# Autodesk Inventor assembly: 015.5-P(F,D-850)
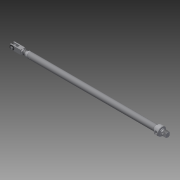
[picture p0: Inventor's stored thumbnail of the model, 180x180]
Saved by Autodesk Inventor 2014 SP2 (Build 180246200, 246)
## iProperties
Category: PARTsolutions
Company: BIMBA
Created: 2020-01
Part Number: 015.5-P(F,D-850)
Catalog Web Link: www.cadenas.de
Description: Original Line Standard Air Cylinders-Standard Air Cylinders
Vendor: BIMBA
Document SubType Name: Assembly
Designer: psadmin
Manufacturer: BIMBA
Title: 015.5-P
Author: Cadenas PARTsolutions
Comments: Standard Air Cylinders
PSOL_IDENT_0: {$CADENAS_DATA\23d-libs\bimba\bimba_brand\bimba_imperial\bimba_full_line\original_line_cylinders\sta
PSOL_IDENT_1: ndard_air_cylinders\standard_air_cylinder_asmtab.prj},331 {VTYP=3D},{STYP=ASSTAB},{NB=015.5-P(F,D-85
PSOL_IDENT_2: 0)},{LINA=015.5-P},{NN=Original Line Standard Air Cylinders},{DATE=23.12.2019 10:36:48},{GEOMDATE=24
PSOL_IDENT_3: .10.2019 09:09:47},{VERSION=},{LINEID=30},{WBVAR=STROKE,ACTING,MNT,DER,NR,BM,CO,OO,VO,M,EE,EEL,K,Q,Y
PSOL_IDENT_4: ,G,T,HL,B,H,SER,SR,NT,W,STPT1,STPT2,STPT3,STPT4,MB,PB,PRC,TB,MN},{WBNUMERIC=STROKE,EEL}  {NB=015.5-P
PSOL_IDENT_5: (F,D-850)},{LINA=015.5-P},{KT=DUMMY},{PN=015.5-P},{PNC=015.5-P(F,D-850)},{PNA=(D-850)},{DASH=-},{BOR
PSOL_IDENT_6: E1=0.43750000},{BORE=7/16\" (01)},{BOREPN=01},{STROKE=5.500},{STROKEALG=[0.011:50/0.001]},{STROKE1=5
PSOL_IDENT_7: .500},{ACTING=},{ACTINGALG= '' , 'Single Acting' , 'R' , 'Reverse Single Acting (R)' , 'D' , 'Double
PSOL_IDENT_8: Acting (D)' },{ACTINGPN=},{MNT=P},{MNTALG= '' , 'Front Nose Mounting' , 'P' , 'Rear Pivot Mounting
PSOL_IDENT_9: (P)' , 'BF' , 'Front Block Mounting (BF)' , 'BR' , 'Rear Block Mounting for Vertical Positioning (BR
PSOL_IDENT_10: )' , 'BFT' , 'Front Block Trunnion Mounting (BFT)' , 'BRT' , 'Rear Block Trunnion Mounting (BRT)' },
PSOL_IDENT_11: {TYPE=},{MNTPN=P},{DER=},{DERALG= '' , 'N/A' },{NR=},{NRALG= '' , 'Round (Standard)' , 'NR' , 'Non-r
PSOL_IDENT_12: otating - Hexagon Rod' },{NRPN=},{BM=},{BMALG= '' , 'N/A' },{BMPN=},{CO=},{COALG= '' , 'N/A' },{OO=}
PSOL_IDENT_13: ,{OOALG= '', 'N/A' },{OOPN=},{VO=Z},{VOALG= 'Z' , 'N/A' },{VOPN=},{OOVOPN=},{M=},{MALG= '', 'Without
PSOL_IDENT_14: Magnet', 'M', 'With Magnet' },{EE=},{EEL=0.000},{EEMAX=44.5000},{EEALG= '', 'Without Extra Extensio
PSOL_IDENT_15: n', 'EE', 'With Extra Extension' },{EELALG=0},{EEPN=},{EEPN1=0.000},{K=},{KALG= '', 'Standard' , 'K'
PSOL_IDENT_16: , 'Ports Rotated 90deg K' },{KPN=},{Q=},{QALG= '' , 'N/A' },{QPN=},{Y=},{YALG= '' , 'Without Pivot
PSOL_IDENT_17: Bushing' , 'Y' , 'With Pivot Bushing' },{YPN=},{YCON=},{F=},{FALG= '', 'Non-Coated (Standard)', 'F',
PSOL_IDENT_18: 'Molycoated' },{FPN=},{G=},{GPN=},{GPN99=},{T=},{TALG= '' , 'Standard -20° to 200°F (-29° to 95°C)'
PSOL_IDENT_19: , 'N' , 'Low Temperature' , 'V' , 'High Temperature' },{NPN=},{VPN=},{HL=},{HLALG= '' , 'N/A' },{B=
PSOL_IDENT_20: },{BALG= '', 'W/out Bumpers' , 'B' , 'W/ Bumpers' },{BPN=},{H=},{HALG= '', 'N/A' },{HPN=},{SER=},{SE
PSOL_IDENT_21: RALG= '' , 'N/A' },{SR=},{SRALG= '' , 'Standard Stainless Steel' },{SRPN=},{SRCON=0},{NT=},{NTPN=},{
PSOL_IDENT_22: W=},{WALG= '' , 'N/A' },{WPN=},{E=},{EALG= '' , 'Standard Seals/Lube' , 'E' , 'Non-Lube Seals/Lube'
PSOL_IDENT_23: },{EPN=},{ST=},{STALG= '' , 'N/A' },{STPT1=},{STPT1ALG= '' , 'N/A' },{STPT2=},{STPT2ALG= '' , 'N/A'
PSOL_IDENT_24: },{STPT3=},{STPT3ALG= '' , 'N/A' },{STPT4=},{STPT4ALG= '' , 'N/A' },{STPN=},{MB=},{MBALG= '' , 'N/A'
PSOL_IDENT_25: },{MBPN=},{MBPNALL=},{MBPNALLREAR=},{PB=},{PBALG= '' , 'Without Pivot Bracket' , 'D-780' , 'D-780'
PSOL_IDENT_26: },{PBPN=},{PBPNALL=D-780},{PRC=F,D-850},{PRCALG= '' , 'W/out Pivot Rod Clevis' , 'F,D-850' , 'D-850
PSOL_IDENT_27: (front)' },{PRCPN=(F,D-850)},{PRCPNALL=D-850},{TB=},{TBALG= '' , 'N/A' },{TBPN=},{TBPNALL=},{MN=},{M
PSOL_IDENT_28: NALG= '' , 'Without Mounting Nut' , 'F,D-801' , 'D-801 (front)' , 'R,D-154' , 'D-154 (rear)', '2xZ'
PSOL_IDENT_29: , 'D-801 (front) & D-154 (rear)' },{MNPN=},{MNCONF=},{MNCONR=},{TLEN=10.8620},{FRAC=12.0900},{RGCON=
PSOL_IDENT_30: },{RGDACCON=},{RHCON=P},{RHCON1=P},{RHCONON=1},{RHACCON=},{FNUTCON=0},{RNUTCON=0},{FNUTPN=D-801},{RN
PSOL_IDENT_31: UTPN=D-154},{FNUTTRANS=0.0000},{RNUTTRANS=0.0000},{VHOLECON=2},{A1=0.6880},{A1N=0.6880},{A1P=1.1880}
PSOL_IDENT_32: ,{A1B=1.1880},{A4=0.2500},{A4N=0.2500},{A4P=0.1880},{A5=0.0200},{A1H=1.188},{A1NH=0.5000},{A1PH=1.18
PSOL_IDENT_33: 80},{A1BH=0.8120},{A1SH=0.0000},{A2H=0.1880},{A2NH=0.1880},{LENGTH=1.7500},{LENGTH1=1.7500},{LENGTH2=
PSOL_IDENT_34: 2.6100},{MUL=10.3400},{MUL11=10.3400},{MUL22=15.84},{MUL33=10.3400},{MUL2=0.9400},{MUL211=0.9400},{M
PSOL_IDENT_35: UL222=1.4400},{MUL233=0.9400},{SSS=11.0000},{RGLEN=0.4580},{RHLEN=0.7700},{SSS1=11.0000},{A13=0.9380
PSOL_IDENT_36: },{DIF=0.0000},{G5=0.0000},{ON=0},{SSADD=0.0000},{BADD=0.0000},{MADD=0.0000},{NVADD=0.0000},{TRACKL=
PSOL_IDENT_37: 10.5520},{TRACKCON=D-74168},{TRIMCON=0},{TRIMCON1=0},{PINCON=D-787},{FSPACE=0.3608},{SPACE=0.0594},{
PSOL_IDENT_38: TEXT=0.1039},{S1=0.7500},{D1=0.4840},{D1N=0.4840},{D1B=0.7380},{D1P=0.0000},{FA=0.560},{RA=0.5600},{
PSOL_IDENT_39: PPATH=standard_air_cylinder_asmtpl.prj},{MATALGHTML=<b>Standard Original Line:</b><dl><dt>Rod:</dt><
PSOL_IDENT_40: dd>- Stainless Steel</dd><dd>&nbsp;&nbsp;(5/16 9/16 Bores)</dd><dd>- High Strength Carbon Steel</dd>
PSOL_IDENT_41: <dd>&nbsp;&nbsp;(3/4 3 Bore)</dd><dd>- Stainless Steel</dd><dd>&nbsp;&nbsp;(X style DXP/DX/DXDE)</dd
PSOL_IDENT_42: ><dt>Bearings:</dt><dd>- Sintered Bronze</dd><dt>Body:</dt><dd>- 304 Stainless Steel</dd><dt>End Cap
PSOL_IDENT_43: s:</dt><dd>- Aluminum</dd><dt>Seals:</dt><dd>- Buna N</dd></dl>},{ASSCFGPRA=01P},{MBPNA=},{MNPNA=},{
PSOL_IDENT_44: PRCPNA=(D-850)},{ASSOPTACC=STPT4},{A=12.09},{HADD=0.0000},{WFL=0},{QADD=0.000},{QADD1=0.190},{TEST=5
PSOL_IDENT_45: .0000},{MNTB=},{STDNUTF=0},{STDNUTR=0},{STRK2D=0},{X2D=2},{STROKESW=5.500},{EESW=0.000},{FCD=0},{BCD=
PSOL_IDENT_46: 0},{RCD=0},{CUSTADD=4.500},{FT=#10-32 UNF-2A},{FT1=#10-32 UNF-2A},{FT2=7/16-20 UNF-2A},{PORT=#10-32}
PSOL_IDENT_47: ,{FT11=3/8-24 UNF-2A},{FT12=7/16-20 UNF-2A},{B1=}
NN: Original Line Standard Air Cylinders
NT: Threaded (Standard)
NB: 015.5-P(F,D-850)
NBSYN: $PNC.
LINA: 015.5-P
PN: 015.5-P
PNA: (D-850)
BORE: 7/16" (01)
STROKE: 5.5
ACTING: Single [Standard]
MNT: Rear Pivot Mounting (P)
DER: N/A
NR: Round (Standard)
BM: N/A
CO: N/A
OO: N/A
VO: N/A
M: Without Magnet
EE: Without Extra Extension
EEL: 0
K: Standard
Q: N/A
Y: Without Pivot Bushing
G: Standard Lube
T: Standard -20° to 200°F (-29° to 95°C)
HL: N/A
B: W/out Bumpers
H: N/A
SER: N/A
SR: Standard Stainless Steel
W: N/A
STPT1: N/A
STPT2: N/A
STPT3: N/A
STPT4: N/A
MB: N/A
PB: Without Pivot Bracket
PRC: D-850 (front)
TB: N/A
MN: Without Mounting Nut
A: 12.09
SUPPLIER: BIMBA
ARTICLENO: 015.5-P(F,D-850)
BOMINFO: 015.5-P
CREATOR: CADENAS GmbH
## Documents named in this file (12)
- p:\temp\worker_7\temp\exporttempdir_2928_84_gfaxY\015_5-P(F,D-850).iam
- p:\temp\worker_7\temp\exporttempdir_2928_84_gfaxY\015_5-P(F,D-850)0000000_0_dummy.ipt
- p:\temp\worker_7\temp\exporttempdir_2928_84_gfaxY\01000-0_rod_guide.ipt
- p:\temp\worker_7\temp\exporttempdir_2928_84_gfaxY\01-10_8622.ipt
- p:\temp\worker_7\temp\exporttempdir_2928_84_gfaxY\01P0000_rear_head.ipt
- p:\temp\worker_7\temp\exporttempdir_2928_84_gfaxY\D-787.ipt
- p:\temp\worker_7\temp\exporttempdir_2928_84_gfaxY\015_5-P0000_rod.ipt
- p:\temp\worker_7\temp\exporttempdir_2928_84_gfaxY\D-850-dummy.ipt
- p:\temp\worker_7\temp\exporttempdir_2928_84_gfaxY\D-14043.ipt
- p:\temp\worker_7\temp\exporttempdir_2928_84_gfaxY\D-12304.ipt
- p:\temp\worker_7\temp\exporttempdir_2928_84_gfaxY\D-5406.ipt
- p:\temp\worker_7\temp\exporttempdir_2928_84_gfaxY\D-5288.ipt
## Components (12 placed, 11 different names)
1. 015_5-P(F,D-850)0000000_0_dummy:1
2. 01000-0_rod_guide:1
3. 01-10_8622:1
4. 01P0000_rear_head:1
5. D-787:1
6. 015_5-P0000_rod:1
7. D-850-dummy:1
8. D-14043:1
9. D-12304:1
10. D-5406:1
11. D-5406:2
12. D-5288:1
